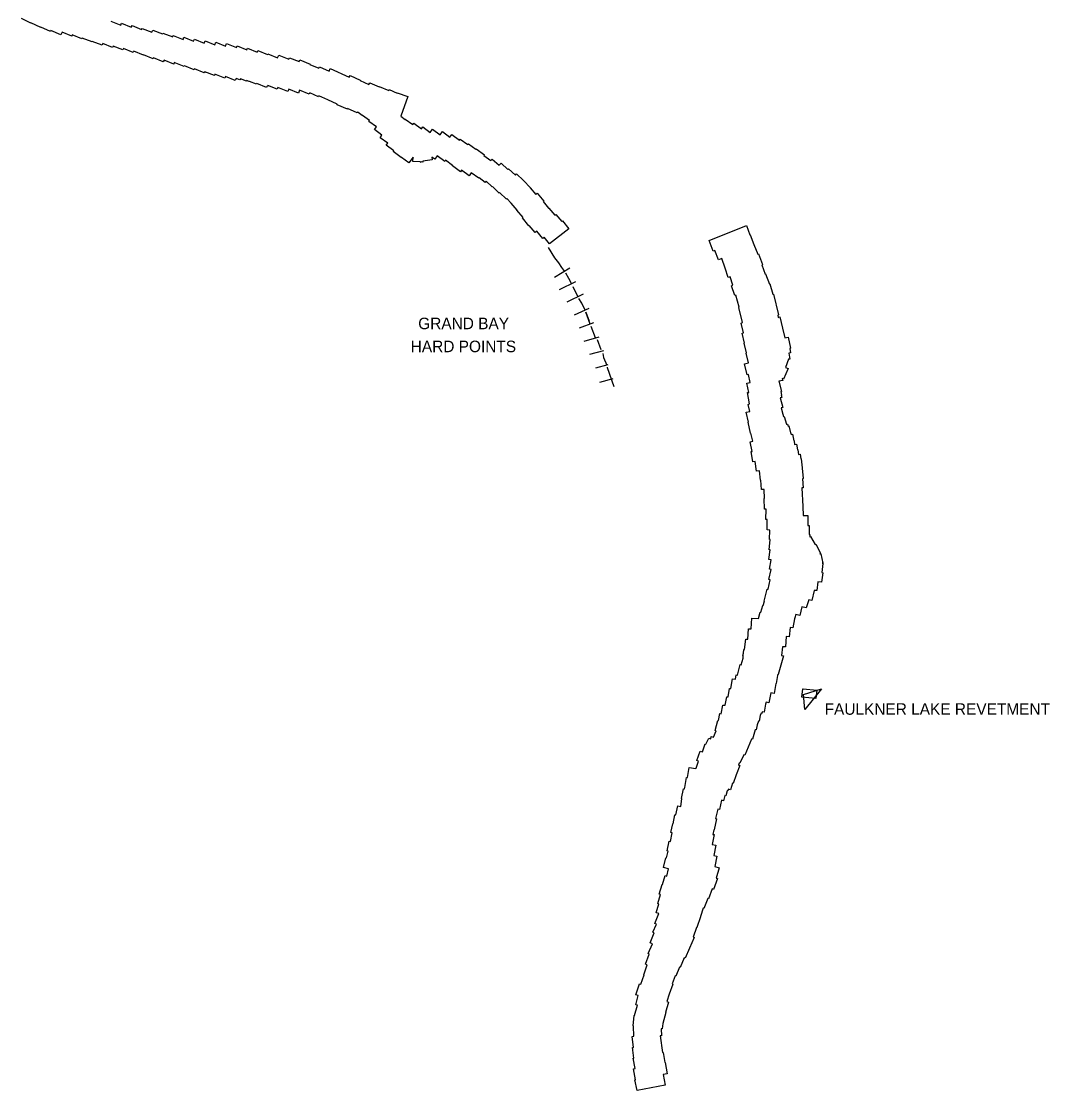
# Model space of a CAD drawing. Extents: x 2650582 to 3923188, y 277893 to 989177.
# Drawn here: x 3284350 to 3298617, y 766782 to 781624 of the extents above; entities that cross this region are included whole.
import ezdxf

# ---------------------------------------------------------------- set-up
doc = ezdxf.new("R2010")
doc.units = 0
doc.layers.add('Level 3', color=7, linetype='Continuous')

msp = doc.modelspace()

# ---------------------------------------------------------------- linework, layer by layer
at = {"layer": 'Level 3'}
for p, q in [((3291962, 778197), (3291747, 778070)), ((3291802, 778274), (3291802, 778274)), ((3292040, 778008), (3291814, 777899)), ((3292003, 777945), (3292073, 777801)), ((3292147, 777836), (3291916, 777725)), ((3292224, 777637), (3292019, 777545)), ((3292286, 777439), (3292087, 777365)), ((3292252, 777393), (3292310, 777236)), ((3292158, 777187), (3292367, 777244)), ((3292337, 777207), (3292392, 777068)), ((3292426, 777051), (3292231, 776998)), ((3292321, 776813), (3292491, 776859)), ((3292374, 776617), (3292563, 776668)), ((3295204, 772282), (3295454, 772360)), ((3295204, 772282), (3295454, 772360)), ((3295221, 772074), (3295204, 772282)), ((3295221, 772074), (3295204, 772282)), ((3295454, 772360), (3295221, 772074)), ((3295454, 772360), (3295221, 772074))]:
    msp.add_line(p, q, dxfattribs=at)
for points in [[(3286747, 780953), (3286613, 781008), (3286608, 780996), (3286472, 781051), (3286464, 781032), (3286329, 781086), (3286319, 781061), (3286184, 781116), (3286180, 781105), (3286045, 781159), (3286044, 781155), (3285908, 781211), (3285902, 781194), (3285766, 781249), (3285757, 781227), (3285622, 781281), (3285614, 781261), (3285479, 781316), (3285469, 781292), (3285333, 781346), (3285330, 781338), (3285194, 781390), (3285190, 781381), (3285055, 781438), (3285048, 781420), (3284914, 781475), (3284899, 781439), (3284760, 781496), (3284753, 781481), (3284620, 781543), (3284619, 781540), (3284483, 781604), (3284479, 781597), (3284350, 781663)], [(3285592, 781628), (3285729, 781573), (3285739, 781598), (3285875, 781543), (3285885, 781567), (3286018, 781512), (3286024, 781527), (3286161, 781473), (3286173, 781503), (3286308, 781449), (3286313, 781461), (3286450, 781407), (3286458, 781428), (3286593, 781373), (3286605, 781404), (3286739, 781348), (3286750, 781378), (3286885, 781323), (3286899, 781356), (3287033, 781300), (3287048, 781336), (3287183, 781281), (3287197, 781317), (3287333, 781261), (3287344, 781286), (3287479, 781231), (3287488, 781253), (3287623, 781197), (3287632, 781218), (3287767, 781163), (3287770, 781171), (3287905, 781117), (3287920, 781155), (3288060, 781098), (3288069, 781119)], [(3288069, 781119), (3288203, 781065), (3288214, 781091), (3288357, 781032), (3288354, 781023), (3288478, 780975), (3288488, 780994), (3288619, 780935), (3288634, 780968), (3288900, 780851), (3288911, 780874), (3289052, 780809), (3289049, 780802), (3289171, 780747), (3289183, 780773), (3289313, 780714), (3289316, 780722), (3289448, 780663), (3289454, 780676), (3289564, 780626), (3289566, 780631), (3289712, 780579), (3289614, 780306)], [(3289023, 780358), (3289011, 780364), (3289007, 780355), (3288876, 780413), (3288873, 780405), (3288730, 780467), (3288733, 780474), (3288601, 780533), (3288602, 780536), (3288479, 780591), (3288473, 780577), (3288351, 780632), (3288343, 780613), (3288210, 780668), (3288195, 780626), (3288060, 780682), (3288047, 780651), (3287908, 780708), (3287897, 780682), (3287770, 780734), (3287765, 780720), (3287757, 780722), (3287751, 780707), (3287617, 780763), (3287612, 780750), (3287513, 780789), (3287512, 780788), (3287475, 780802), (3287472, 780794), (3287389, 780828), (3287382, 780812), (3287329, 780832), (3287316, 780801), (3287181, 780857), (3287173, 780835), (3287036, 780889), (3287029, 780871), (3286894, 780925), (3286888, 780910), (3286752, 780966), (3286747, 780953)], [(3291676, 778535), (3291605, 778627), (3291587, 778612), (3291504, 778712), (3291481, 778692), (3291397, 778792), (3291392, 778787), (3291302, 778895), (3291310, 778901), (3291226, 779001), (3291227, 779002), (3291144, 779102), (3291145, 779102), (3291087, 779164), (3291080, 779157), (3290986, 779247), (3290980, 779241), (3290886, 779331), (3290884, 779329), (3290801, 779408), (3290783, 779386), (3290704, 779454), (3290698, 779446), (3290593, 779523), (3290563, 779482), (3290458, 779558), (3290443, 779537), (3290330, 779619), (3290333, 779623), (3290236, 779695), (3290225, 779679), (3290120, 779756), (3290086, 779709), (3290044, 779739), (3290050, 779702), (3289922, 779682), (3289922, 779671), (3289899, 779673), (3289893, 779665), (3289882, 779674), (3289782, 779680), (3289785, 779738), (3289727, 779658), (3289622, 779735), (3289621, 779733), (3289508, 779816), (3289517, 779828), (3289412, 779904), (3289433, 779933), (3289327, 780009), (3289353, 780045), (3289248, 780121), (3289276, 780159), (3289171, 780236), (3289180, 780248), (3289083, 780319), (3289080, 780316), (3289023, 780358)], [(3289614, 780306), (3289673, 780263), (3289676, 780268), (3289781, 780192), (3289795, 780210), (3289900, 780134), (3289918, 780158), (3290023, 780082), (3290055, 780126), (3290161, 780050), (3290192, 780093), (3290297, 780017), (3290324, 780053), (3290429, 779977), (3290439, 779990), (3290544, 779914), (3290552, 779925), (3290657, 779849), (3290662, 779855), (3290775, 779773), (3290766, 779761), (3290862, 779691), (3290880, 779712), (3290978, 779628), (3291007, 779657), (3291100, 779567), (3291111, 779579), (3291205, 779489), (3291222, 779506), (3291317, 779416), (3291413, 779314), (3291410, 779311), (3291487, 779220), (3291508, 779237), (3291597, 779130), (3291589, 779123), (3291666, 779031), (3291667, 779032), (3291750, 778932), (3291765, 778944), (3291847, 778846), (3291858, 778855), (3291945, 778744), (3291676, 778535)], [(3294657, 773576), (3294698, 773744), (3294713, 773741), (3294741, 773873), (3294723, 773878), (3294753, 774017), (3294732, 774021), (3294752, 774149), (3294723, 774153), (3294738, 774287), (3294726, 774289), (3294738, 774433), (3294729, 774434), (3294737, 774562), (3294697, 774564), (3294700, 774708), (3294681, 774708), (3294682, 774851), (3294661, 774852), (3294658, 775000), (3294661, 775000), (3294657, 775127), (3294617, 775126), (3294608, 775254), (3294605, 775254), (3294591, 775384), (3294551, 775379), (3294531, 775513), (3294501, 775508), (3294476, 775653), (3294489, 775655), (3294464, 775789), (3294497, 775796), (3294473, 775910), (3294468, 775909), (3294433, 776061), (3294437, 776062), (3294406, 776198), (3294456, 776209), (3294432, 776305), (3294455, 776313), (3294423, 776472), (3294442, 776474), (3294418, 776602), (3294464, 776613), (3294437, 776722), (3294421, 776718), (3294385, 776871), (3294438, 776886), (3294406, 777020), (3294410, 777021), (3294377, 777155), (3294385, 777159), (3294352, 777294), (3294370, 777300), (3294338, 777437), (3294356, 777442), (3294306, 777654), (3294309, 777656), (3294263, 777825), (3294248, 777820), (3294203, 777953), (3294223, 777961), (3294184, 778078), (3294158, 778068), (3294113, 778196), (3294116, 778198), (3294067, 778332), (3294023, 778316), (3293970, 778445), (3293948, 778435), (3293892, 778581), (3294410, 778792)], [(3294410, 778792), (3294459, 778659), (3294464, 778662), (3294515, 778527), (3294513, 778526), (3294567, 778393), (3294576, 778397), (3294632, 778249), (3294625, 778244), (3294670, 778117), (3294676, 778121), (3294728, 777977), (3294735, 777980), (3294776, 777836), (3294788, 777839), (3294857, 777549), (3294844, 777545), (3294850, 777515), (3294872, 777521)], [(3291657, 778483), (3291749, 778341), (3291802, 778274), (3291846, 778207), (3291886, 778153)], [(3291901, 778133), (3291943, 778059), (3291983, 777981)], [(3292173, 777613), (3292125, 777711), (3292085, 777779)], [(3292243, 777423), (3292183, 777586), (3292229, 777462), (3292229, 777462)], [(3294872, 777521), (3294912, 777367), (3294910, 777366), (3294943, 777232), (3294988, 777239), (3295021, 777086), (3295013, 777084), (3295023, 777022), (3294998, 777017), (3295013, 776937), (3294995, 776933), (3294950, 776820), (3294987, 776805), (3294926, 776659), (3294906, 776667), (3294913, 776641), (3294862, 776628), (3294896, 776488), (3294886, 776485)], [(3292418, 777013), (3292427, 776958), (3292473, 776854)], [(3292478, 776824), (3292479, 776821), (3292572, 776555)], [(3294886, 776485), (3294898, 776434), (3294894, 776433), (3294901, 776405), (3294880, 776400), (3294914, 776263), (3294894, 776259), (3294916, 776172), (3294917, 776173), (3294926, 776137), (3294936, 776140), (3294964, 776032), (3294981, 776035), (3294987, 776007)], [(3294987, 776007), (3294997, 776009), (3295026, 775896), (3295029, 775897), (3295030, 775891), (3295050, 775894), (3295067, 775802)], [(3295067, 775802), (3295071, 775802), (3295078, 775750), (3295105, 775754), (3295118, 775675), (3295125, 775677), (3295134, 775612), (3295155, 775616), (3295164, 775550), (3295171, 775551), (3295184, 775425), (3295182, 775424), (3295196, 775277), (3295188, 775276), (3295199, 775150), (3295178, 775148), (3295191, 774890), (3295195, 774889), (3295197, 774766), (3295260, 774767), (3295261, 774627), (3295281, 774627), (3295282, 774500), (3295289, 774500), (3295289, 774470), (3295298, 774475), (3295365, 774361), (3295372, 774366), (3295437, 774242), (3295427, 774233), (3295443, 774234), (3295470, 774105), (3295460, 774102), (3295471, 774100), (3295457, 773972), (3295468, 773971), (3295452, 773840), (3295403, 773845), (3295385, 773722), (3295349, 773726), (3295319, 773585), (3295274, 773594), (3295240, 773483), (3295180, 773497), (3295150, 773375), (3295094, 773390), (3295081, 773345)], [(3294576, 773334), (3294603, 773425), (3294612, 773423), (3294639, 773517), (3294644, 773516), (3294660, 773575), (3294657, 773576)], [(3294369, 772855), (3294372, 772904), (3294385, 772905), (3294401, 773050), (3294428, 773049), (3294441, 773194), (3294474, 773193), (3294483, 773338), (3294576, 773334)], [(3295081, 773345), (3295079, 773332), (3295076, 773332), (3295054, 773204), (3295016, 773208), (3295004, 773080), (3294961, 773084), (3294950, 772941), (3294911, 772943), (3294899, 772823)], [(3294257, 772492), (3294269, 772554), (3294288, 772550), (3294322, 772696), (3294338, 772692), (3294364, 772783), (3294366, 772820), (3294359, 772822), (3294369, 772855)], [(3294899, 772823), (3294925, 772816), (3294850, 772559), (3294848, 772559), (3294843, 772542), (3294822, 772431), (3294820, 772432), (3294793, 772293), (3294749, 772302), (3294723, 772164), (3294683, 772172), (3294675, 772147), (3294654, 772033), (3294629, 772038), (3294622, 772018), (3294614, 772020), (3294601, 771988), (3294586, 771908), (3294578, 771909), (3294557, 771858), (3294545, 771789), (3294530, 771791), (3294494, 771658), (3294482, 771661), (3294387, 771438), (3294375, 771443), (3294317, 771325), (3294310, 771328)], [(3293978, 771781), (3294013, 771920), (3294023, 771918), (3294040, 772015), (3294058, 772013), (3294083, 772134), (3294116, 772130), (3294140, 772250), (3294157, 772249), (3294177, 772363), (3294195, 772362), (3294219, 772499), (3294257, 772492)], [(3295191, 772361), (3295196, 772360), (3295386, 772341), (3295375, 772223), (3295375, 772223), (3295177, 772241), (3295177, 772243), (3295191, 772361)], [(3295191, 772361), (3295196, 772360), (3295386, 772341), (3295375, 772223), (3295375, 772223), (3295177, 772241), (3295177, 772243), (3295191, 772361)], [(3293707, 771251), (3293709, 771259), (3293712, 771258), (3293746, 771354), (3293721, 771363), (3293769, 771495), (3293801, 771483), (3293838, 771594), (3293847, 771591), (3293888, 771676), (3293915, 771666), (3293922, 771696), (3293952, 771688), (3293992, 771778), (3293978, 771781)], [(3293499, 770727), (3293515, 770834), (3293511, 770835), (3293538, 770972), (3293553, 770970), (3293556, 770991), (3293580, 771128), (3293591, 771126), (3293615, 771267), (3293707, 771251)], [(3294310, 771328), (3294301, 771301), (3294317, 771295), (3294269, 771163), (3294268, 771164), (3294225, 771046), (3294218, 771049), (3294189, 770955), (3294156, 770966), (3294151, 770943), (3294142, 770945), (3294124, 770873), (3294112, 770876)], [(3294112, 770876), (3294094, 770806), (3294065, 770813), (3294038, 770684), (3294012, 770688), (3293983, 770557), (3293994, 770554), (3293962, 770402), (3293957, 770403)], [(3293157, 769250), (3293195, 769375), (3293179, 769380), (3293217, 769504), (3293198, 769510), (3293239, 769644), (3293245, 769643), (3293282, 769766), (3293304, 769760), (3293329, 769861), (3293259, 769879), (3293293, 770015), (3293301, 770013), (3293324, 770105), (3293310, 770109), (3293336, 770246), (3293357, 770242), (3293379, 770360), (3293363, 770363), (3293387, 770485), (3293394, 770484), (3293419, 770610), (3293432, 770608), (3293457, 770735), (3293499, 770727)], [(3293957, 770403), (3293945, 770339), (3293961, 770335), (3293936, 770198), (3293986, 770188), (3293960, 770045), (3294001, 770037), (3293972, 769891), (3294032, 769873), (3293991, 769731), (3294008, 769724), (3293951, 769575), (3293936, 769581), (3293886, 769442), (3293873, 769447), (3293821, 769311), (3293811, 769314), (3293772, 769197), (3293774, 769196), (3293720, 769046), (3293718, 769045), (3293669, 768913), (3293685, 768905), (3293621, 768758), (3293619, 768759), (3293558, 768621), (3293548, 768625), (3293489, 768493), (3293481, 768495), (3293431, 768372), (3293423, 768375), (3293382, 768264), (3293389, 768260), (3293337, 768119), (3293307, 768017), (3293329, 768011), (3293289, 767865), (3293291, 767864), (3293250, 767715), (3293243, 767641), (3293229, 767641), (3293231, 767542), (3293213, 767540), (3293246, 767309), (3293255, 767310), (3293278, 767170), (3293284, 767171), (3293311, 767016), (3293257, 767004), (3293283, 766858), (3292894, 766782)], [(3292894, 766782), (3292863, 766931), (3292871, 766933), (3292843, 767086), (3292864, 767091), (3292840, 767233), (3292848, 767234), (3292827, 767379), (3292841, 767382), (3292823, 767535), (3292848, 767539), (3292843, 767678), (3292838, 767680), (3292852, 767825), (3292859, 767823), (3292897, 767967), (3292874, 767974), (3292907, 768100), (3292874, 768110), (3292928, 768265), (3292945, 768258), (3292991, 768388), (3292986, 768390), (3293034, 768527), (3293009, 768537), (3293060, 768677), (3293045, 768684), (3293105, 768819), (3293073, 768834), (3293131, 768972), (3293111, 768982), (3293161, 769094), (3293141, 769102), (3293193, 769239), (3293157, 769250)]]:
    msp.add_lwpolyline(points, dxfattribs=at)

# ---------------------------------------------------------------- texts
for s, p in [('GRAND BAY', (3289856, 777351)), ('HARD POINTS', (3289752, 777032)), ('FAULKNER LAKE REVETMENT', (3295495, 771999))]:
    msp.add_text(s, height=160, dxfattribs=at).set_placement(p)

doc.saveas('drawing.dxf')
